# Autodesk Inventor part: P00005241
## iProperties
Shininess: 64.0
Length Units: 11269
Angle Units: 11279
Time Units: 11290
Mass Units: 11283
Length Display Precision: 3
Angle Display Precision: 2
Compacted: True
Part Number: P00005241
Document SubType Name: Modeling
Created: 2004-01
Material: Stahl (schweißbar)
Designer: Mittelmeyer
Manufacturer: Standard
Standards Organization: Custom
Density: 0.0
Volumn: 0.0
Area: 0.0
PropertySet Name: Model Information
Control State: 0
Master: False
Checked Out: False
Author: Mittelmeyer
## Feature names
1. Basis1
2. Extrusion1
3. Extrusion2
